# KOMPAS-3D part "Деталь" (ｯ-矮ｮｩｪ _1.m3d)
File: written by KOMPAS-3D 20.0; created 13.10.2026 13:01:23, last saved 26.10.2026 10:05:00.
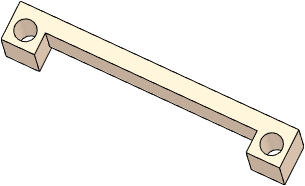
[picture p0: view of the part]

Document properties: Полное имя файла: D:\RicWork\Project-EPS32\box_compas\корпус\п-стойка_1.m3d

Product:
- Part/product: Деталь
    Масса: 0.0133591

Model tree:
1. Эскиз:1
2. Элемент выдавливания:1
     Расстояние 1 = 11
3. Эскиз:2  (with: Элемент выдавливания:1)
4. Элемент выдавливания:2
     Расстояние 2 = 11
5. Массив по сетке:1  (with: Элемент выдавливания:2, Эскиз:2)  (2 pattern instances)
     Шаг 1 = 10; Угол раствора = -90; Шаг 2 = 44.2
6. Эскиз:3  (with: Элемент выдавливания:1)
7. Элемент выдавливания:3
     Расстояние 2 = 2
8. Эскиз:4  (with: Элемент выдавливания:1)
9. Элемент выдавливания:4
     Расстояние 2 = 2
10. Элемент выдавливания:5  (with: Элемент выдавливания:3)
     Расстояние 1 = 2
11. Элемент выдавливания:6  (with: Элемент выдавливания:1)
     Расстояние 1 = 1
12. Элемент выдавливания:7  (with: Элемент выдавливания:1)
     Расстояние 1 = 1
